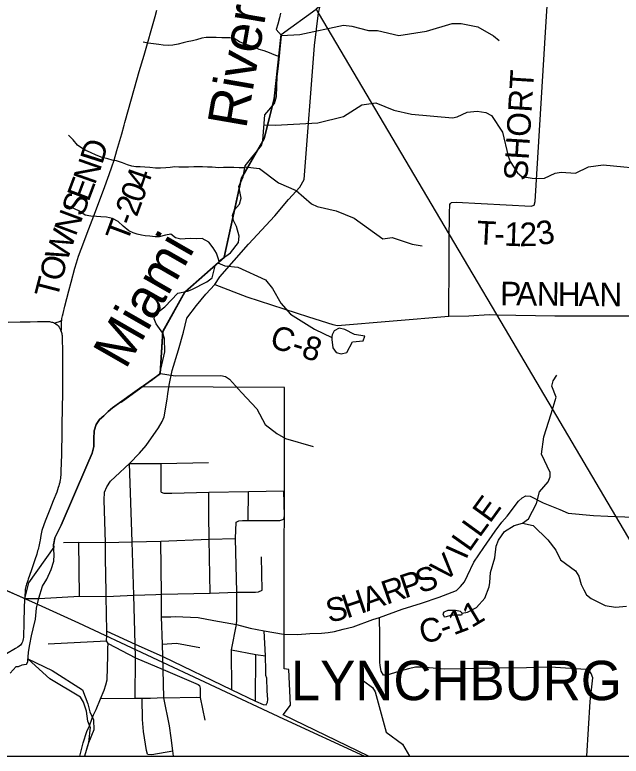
# Model space of a CAD drawing. Extents: x 0 to 48.6, y 0 to 22.
# Drawn here: x 3.311 to 4.768, y 14.1 to 15.882 of the extents above; entities that cross this region are included whole.
import ezdxf

# ---------------------------------------------------------------- set-up
doc = ezdxf.new("R2010")
doc.units = 0
for name, color, linetype in [('GM_X_City_Street', 7, 'Continuous'), ('GM_X_Corporation', 7, 'Continuous'), ('GM_X_Corporation_Text', 7, 'Continuous'), ('GM_X_County_Road', 7, 'Continuous'), ('GM_X_County_Road_Text', 7, 'Continuous'), ('GM_X_Major_River', 7, 'Continuous'), ('GM_X_Major_River_Text', 7, 'Continuous'), ('GM_X_Minor_Lake', 7, 'Continuous'), ('GM_X_Minor_River', 7, 'Continuous'), ('GM_X_Rail_Line', 7, 'Continuous'), ('GM_X_State_Route', 7, 'Continuous'), ('GM_X_Township_Road', 7, 'Continuous'), ('GM_X_Township_Road_Text', 7, 'Continuous'), ('SH_Data', 7, 'Continuous')]:
    doc.layers.add(name, color=color, linetype=linetype)

msp = doc.modelspace()

# ---------------------------------------------------------------- linework, layer by layer
at = {"layer": 'GM_X_City_Street'}
for p, q in [((3.6625, 14.7345), (3.6625, 14.8032)), ((3.8714, 14.6664), (3.8718, 14.736)), ((3.4662, 14.4845), (3.4646, 14.6148)), ((3.9053, 14.4987), (3.9036, 14.5793)), ((3.663, 14.4351), (3.6631, 14.4803)), ((3.3907, 14.3702), (3.5312, 14.3769)), ((3.889, 14.2321), (3.89, 14.3448)), ((3.7564, 14.2411), (3.7669, 14.1866))]:
    msp.add_line(p, q, dxfattribs=at)
for points in [[(3.586, 14.8032), (3.6625, 14.8032), (3.7764, 14.8056)], [(3.6002, 14.2383), (3.6006, 14.3367), (3.6, 14.3695), (3.5968, 14.4867), (3.5924, 14.6152), (3.586, 14.8032)], [(3.6625, 14.7345), (3.6686, 14.7321), (3.6879, 14.7325), (3.777, 14.7349), (3.8718, 14.736), (3.957, 14.7382)], [(3.9567, 14.6695), (3.9585, 14.6779), (3.957, 14.7382)], [(3.7798, 14.4922), (3.7778, 14.6217), (3.777, 14.6803), (3.777, 14.7349)], [(3.8429, 14.6627), (3.8492, 14.6656), (3.8575, 14.6664), (3.8714, 14.6664), (3.9478, 14.6665), (3.9567, 14.6695)], [(3.832, 14.2594), (3.8317, 14.3557), (3.8433, 14.4162), (3.8443, 14.427), (3.8444, 14.4941), (3.8409, 14.6235), (3.8429, 14.6627)], [(3.4274, 14.6139), (3.4646, 14.6148), (3.5285, 14.614), (3.5924, 14.6152), (3.6612, 14.6165), (3.7778, 14.6217), (3.8409, 14.6235)], [(3.6631, 14.4803), (3.6631, 14.4894), (3.6612, 14.6165)], [(3.5478, 14.4847), (3.5968, 14.4867), (3.6494, 14.4887), (3.6631, 14.4894), (3.7798, 14.4922), (3.8444, 14.4941), (3.8894, 14.494), (3.8963, 14.4953), (3.9053, 14.4987)], [(3.3688, 14.4789), (3.4662, 14.4845), (3.5299, 14.4839), (3.5478, 14.4847)], [(3.663, 14.4351), (3.6858, 14.4352), (3.6962, 14.4355), (3.7516, 14.4337), (3.7885, 14.4263), (3.8433, 14.4162), (3.8758, 14.4077), (3.91, 14.4016)], [(3.6691, 14.2402), (3.6671, 14.3086), (3.6665, 14.3392), (3.6652, 14.369), (3.663, 14.4351)], [(3.532, 14.4006), (3.6, 14.3695), (3.6665, 14.3392), (3.832, 14.2594), (3.889, 14.2321), (3.9073, 14.2244), (3.9147, 14.2234)], [(3.9137, 14.3062), (3.9127, 14.341), (3.91, 14.4016)], [(3.5346, 14.3706), (3.6006, 14.3367), (3.6671, 14.3086), (3.7514, 14.2726), (3.7543, 14.27), (3.7564, 14.2635), (3.7564, 14.2411)], [(3.6652, 14.369), (3.6989, 14.3713), (3.7549, 14.3615)], [(3.8317, 14.3557), (3.89, 14.3448), (3.9127, 14.341)], [(3.9147, 14.2234), (3.9175, 14.2298), (3.9185, 14.2365), (3.9172, 14.2567), (3.9163, 14.2875), (3.914, 14.2942), (3.9137, 14.3062)], [(3.6691, 14.2402), (3.7467, 14.2416), (3.7564, 14.2411)], [(3.6295, 14.1049), (3.6273, 14.1133), (3.6197, 14.1594), (3.6175, 14.1879), (3.617, 14.2387)], [(3.6295, 14.1049), (3.6399, 14.104), (3.6901, 14.1128)]]:
    msp.add_lwpolyline(points, dxfattribs=at)
at = {"layer": 'GM_X_Corporation'}
msp.add_lwpolyline([(5.0944, 14.1), (8.9, 14.1), (8.9, 19.5692), (8.5348, 19.2897), (7.2261, 18.2847), (6.9471, 18.0777), (6.5365, 17.7727), (5.8387, 17.2541), (5.5264, 17.0064), (4.6225, 16.3345), (4.044, 15.9033), (4.0346, 15.8959), (4.0398, 15.887), (4.3544, 15.3539), (4.4679, 15.1616), (4.7542, 14.6766)], close=True, dxfattribs=at)
for points in [[(3.2996, 14.2996), (3.3136, 14.3153), (3.3197, 14.3159), (3.3281, 14.3199), (3.3384, 14.3209), (3.3419, 14.3265), (3.3432, 14.3497), (3.3465, 14.3687), (3.3504, 14.3894), (3.3549, 14.4061), (3.3603, 14.4295), (3.3625, 14.4556), (3.3686, 14.4795), (3.377, 14.5086), (3.3872, 14.5255), (3.3983, 14.5488), (3.4048, 14.5688), (3.405, 14.584), (3.404, 14.6084), (3.4053, 14.6156), (3.407, 14.625), (3.422, 14.6555), (3.4837, 14.7987), (3.4964, 14.8285), (3.5005, 14.8447), (3.5009, 14.8629), (3.5012, 14.8819), (3.5061, 14.897), (3.5143, 14.909), (3.5243, 14.9183), (3.5348, 14.9284), (3.5452, 14.9373), (3.66, 15.0199), (3.6661, 15.1216), (3.7191, 15.2163), (3.814, 15.2998), (3.8557, 15.4901), (3.9098, 15.5849), (3.9337, 15.6801), (3.9507, 15.8348), (4.0346, 15.8959)], [(3.2996, 14.2996), (3.3136, 14.3153), (3.3197, 14.3159), (3.3281, 14.3199), (3.3384, 14.3209), (3.3419, 14.3265), (3.3432, 14.3497), (3.3465, 14.3687), (3.3504, 14.3894), (3.3549, 14.4061), (3.3603, 14.4295), (3.3625, 14.4556), (3.3686, 14.4795), (3.377, 14.5086), (3.3872, 14.5255), (3.3983, 14.5488), (3.4048, 14.5688), (3.405, 14.584), (3.404, 14.6084), (3.4053, 14.6156), (3.407, 14.625), (3.422, 14.6555), (3.4837, 14.7987), (3.4964, 14.8285), (3.5005, 14.8447), (3.5009, 14.8629), (3.5012, 14.8819), (3.5061, 14.897), (3.5143, 14.909), (3.5243, 14.9183), (3.5348, 14.9284), (3.5452, 14.9373), (3.66, 15.0199), (3.6661, 15.1216), (3.7191, 15.2163), (3.814, 15.2998), (3.8557, 15.4901), (3.9098, 15.5849), (3.9337, 15.6801), (3.9507, 15.8348), (4.0346, 15.8959)], [(3.3067, 14.3077), (3.3137, 14.3153), (3.3197, 14.3159), (3.3281, 14.3199), (3.3325, 14.3203), (3.3384, 14.3209), (3.3419, 14.3265), (3.3423, 14.334), (3.4003, 14.3059), (3.4732, 14.2593), (3.4859, 14.2261), (3.491, 14.2065), (3.4996, 14.1874), (3.5003, 14.1637), (3.4879, 14.1319), (3.4778, 14.1), (4.1608, 14.1), (3.9556, 14.1993), (3.9729, 14.2227), (3.9691, 14.3083), (3.9577, 14.3098), (3.9588, 14.9859), (3.6159, 14.9882), (3.5452, 14.9373), (3.5348, 14.9284), (3.5243, 14.9183), (3.5143, 14.909), (3.5061, 14.897), (3.5012, 14.8819), (3.5009, 14.8629), (3.5005, 14.8447), (3.4964, 14.8285), (3.4837, 14.7987), (3.422, 14.6555), (3.407, 14.625), (3.404, 14.6084), (3.4043, 14.6023), (3.3438, 14.5166), (3.3339, 14.4793), (3.0597, 14.5973)]]:
    msp.add_lwpolyline(points, dxfattribs=at)
at = {"layer": 'GM_X_County_Road'}
for p, q in [((3.3345, 14.4837), (3.3341, 14.4788)), ((3.91, 14.4016), (3.9564, 14.3934))]:
    msp.add_line(p, q, dxfattribs=at)
for points in [[(4.6086, 15.1588), (4.64, 15.1582), (4.8348, 15.1585), (4.9035, 15.1586), (4.9331, 15.1596), (5.071, 15.181), (5.1203, 15.1895), (5.1743, 15.1992), (5.2077, 15.2059), (5.2218, 15.2088), (5.2271, 15.216), (5.2317, 15.2361), (5.2617, 15.7172), (5.2803, 16.0116), (5.7212, 16.011), (6.0742, 16.1743), (6.2545, 16.2661)], [(3.7914, 15.2335), (3.8685, 15.2041), (4.016, 15.1564), (4.0751, 15.1376), (4.0861, 15.1349), (4.3538, 15.1576), (4.4016, 15.1589), (4.4502, 15.1614), (4.4681, 15.1611), (4.6086, 15.1588)], [(3.2944, 15.1433), (3.3236, 15.1437), (3.3472, 15.1442), (3.3652, 15.1445), (3.382, 15.1448), (3.3888, 15.1447), (3.3937, 15.1445), (3.3961, 15.1441), (3.399, 15.1436), (3.4014, 15.1429), (3.4036, 15.1421), (3.4056, 15.1411)], [(3.4056, 15.1411), (3.4063, 15.1408), (3.4094, 15.1389), (3.4123, 15.1366), (3.4149, 15.1341), (3.4172, 15.1313), (3.4191, 15.1283), (3.4208, 15.125), (3.4223, 15.1212)], [(3.4223, 15.1212), (3.4235, 15.1164), (3.4238, 15.114), (3.4243, 15.1109), (3.4245, 15.1072), (3.4248, 15.1029), (3.4251, 15.0744), (3.4256, 15.0185), (3.4255, 14.9744), (3.4239, 14.8967), (3.4233, 14.8619), (3.4229, 14.8433), (3.4226, 14.8272), (3.4219, 14.8026), (3.4218, 14.7971), (3.4216, 14.793), (3.4215, 14.7899), (3.4214, 14.7858), (3.4212, 14.7799), (3.421, 14.7757), (3.4206, 14.7716), (3.4202, 14.7671), (3.4197, 14.764), (3.4192, 14.7604), (3.4185, 14.7575), (3.4176, 14.7538), (3.4163, 14.7498), (3.4151, 14.7455), (3.4114, 14.735), (3.403, 14.7136), (3.3946, 14.6929), (3.3837, 14.6651), (3.3806, 14.6564), (3.3786, 14.6509), (3.3773, 14.6475), (3.3758, 14.6427), (3.3749, 14.6382), (3.3741, 14.6348), (3.3734, 14.6306), (3.3724, 14.625), (3.3715, 14.6196), (3.3708, 14.6158), (3.3701, 14.6123), (3.3692, 14.6079), (3.3684, 14.6044), (3.3674, 14.6007), (3.3665, 14.5971), (3.3655, 14.5937), (3.3632, 14.5858), (3.3584, 14.5717), (3.3496, 14.5459), (3.3429, 14.5258), (3.3419, 14.5224), (3.3404, 14.5176), (3.3391, 14.5132), (3.3382, 14.5103), (3.3373, 14.5076), (3.3366, 14.5045), (3.3359, 14.5012), (3.3357, 14.4984), (3.3345, 14.4837)], [(3.9564, 14.3934), (3.9901, 14.3924), (4.0193, 14.3947), (4.0477, 14.3953), (4.0633, 14.3974), (4.0788, 14.3998), (4.0996, 14.405), (4.1236, 14.4113), (4.1706, 14.4283), (4.1872, 14.4331), (4.2412, 14.4531), (4.2875, 14.4682), (4.33, 14.4823), (4.3721, 14.4979), (4.3815, 14.5077), (4.3915, 14.5191), (4.3982, 14.5345), (4.4133, 14.5664), (4.4378, 14.6016), (4.4649, 14.6406), (4.4813, 14.6622), (4.4939, 14.6769), (4.5042, 14.6905), (4.5129, 14.7029), (4.5211, 14.7128), (4.5297, 14.721), (4.5387, 14.7255), (4.549, 14.7251), (4.5805, 14.7087), (4.6203, 14.6931), (4.6407, 14.6845), (4.701, 14.6783), (4.7354, 14.6767), (4.7544, 14.676), (4.8433, 14.6729)], [(3.3341, 14.4788), (3.3332, 14.4543), (3.3326, 14.4245), (3.3321, 14.4083), (3.3318, 14.399), (3.3314, 14.3872), (3.3312, 14.385), (3.3309, 14.3818), (3.3301, 14.3782), (3.329, 14.3748), (3.3275, 14.3715), (3.3259, 14.369), (3.324, 14.3667), (3.3213, 14.3642), (3.3179, 14.3617), (3.3126, 14.3586), (3.2903, 14.3464)], [(3.3341, 14.4788), (3.3512, 14.4788), (3.3688, 14.4789)]]:
    msp.add_lwpolyline(points, dxfattribs=at)
at = {"layer": 'GM_X_Major_River'}
for points in [[(3.949, 15.8858), (3.9468, 15.8752), (3.9423, 15.8598), (3.939, 15.8466), (3.9516, 15.8321)], [(3.5649, 14.9509), (3.5728, 14.9568), (3.6132, 14.9861), (3.6416, 15.0052), (3.6594, 15.0198), (3.6711, 15.0721), (3.6703, 15.1043), (3.6663, 15.1169), (3.6507, 15.1391), (3.6455, 15.1513), (3.6468, 15.1615), (3.6709, 15.1802), (3.7021, 15.2132), (3.7257, 15.2179), (3.7359, 15.2215), (3.7722, 15.2401), (3.7845, 15.2498), (3.7921, 15.2789), (3.8044, 15.292), (3.8289, 15.3103), (3.8478, 15.3351), (3.8499, 15.3499), (3.8437, 15.3735), (3.8359, 15.3876), (3.8334, 15.3998), (3.8385, 15.413), (3.8505, 15.4269), (3.8545, 15.4413), (3.8491, 15.4691), (3.8593, 15.4928), (3.8642, 15.519), (3.9035, 15.5678), (3.9063, 15.5799), (3.9116, 15.6417), (3.9344, 15.6691), (3.9395, 15.6857), (3.9409, 15.7339), (3.9446, 15.7585), (3.9516, 15.8321)], [(3.6608, 15.0196), (3.6669, 15.1212), (3.7199, 15.216), (3.8149, 15.2994), (3.8565, 15.4898), (3.9106, 15.5846), (3.9345, 15.6798), (3.9515, 15.8345)], [(3.5666, 14.9513), (3.6608, 15.0196)]]:
    msp.add_lwpolyline(points, dxfattribs=at)
at = {"layer": 'GM_X_Minor_Lake'}
for points in [[(4.0725, 15.1017), (4.0748, 15.0812), (4.0827, 15.0705), (4.0952, 15.0669), (4.1085, 15.0706), (4.1221, 15.0958), (4.1479, 15.0985), (4.1515, 15.1099), (4.1265, 15.114), (4.1039, 15.126), (4.0903, 15.1288), (4.0777, 15.1225)], [(4.0777, 15.1225), (4.0733, 15.1131), (4.0727, 15.1086), (4.0725, 15.1017)], [(4.3426, 14.4347), (4.3479, 14.4361), (4.3582, 14.439), (4.3658, 14.4396), (4.3734, 14.4398), (4.378, 14.4397), (4.3829, 14.44), (4.3856, 14.4407), (4.386, 14.4434), (4.3815, 14.4476), (4.3736, 14.4497), (4.3672, 14.4502), (4.3573, 14.4504), (4.3512, 14.4505), (4.3455, 14.4476), (4.3413, 14.4458), (4.3393, 14.442)], [(4.3393, 14.442), (4.3426, 14.4347)]]:
    msp.add_lwpolyline(points, dxfattribs=at)
at = {"layer": 'GM_X_Minor_River'}
for points in [[(3.9516, 15.8321), (3.9957, 15.8346), (4.1003, 15.8572), (4.1208, 15.855), (4.1605, 15.8443), (4.1821, 15.8441), (4.2331, 15.8321), (4.3, 15.8426), (4.3617, 15.8609), (4.3834, 15.8614), (4.4231, 15.8533), (4.4611, 15.8316), (4.4747, 15.8204)], [(3.9468, 15.7808), (3.9339, 15.7862), (3.923, 15.7909), (3.9097, 15.7956), (3.898, 15.7984), (3.8871, 15.8035), (3.8765, 15.8074), (3.8644, 15.8114), (3.8504, 15.8173), (3.8376, 15.825), (3.8277, 15.8271), (3.8179, 15.8268), (3.8084, 15.8269), (3.7947, 15.8279), (3.7799, 15.8273), (3.7704, 15.8274), (3.7597, 15.826), (3.7475, 15.822), (3.738, 15.8195), (3.7247, 15.817), (3.7151, 15.8145), (3.7033, 15.8112), (3.69, 15.8095), (3.679, 15.8085), (3.6672, 15.809), (3.657, 15.8107), (3.6441, 15.812), (3.6308, 15.814), (3.6187, 15.8165)], [(3.9096, 15.6177), (3.9371, 15.6167), (4.0389, 15.6223), (4.1001, 15.6375), (4.1445, 15.6658), (4.1783, 15.6707), (4.2217, 15.6527), (4.2641, 15.6435), (4.3623, 15.6343), (4.3737, 15.6365), (4.3973, 15.648), (4.4213, 15.6503), (4.4421, 15.6474), (4.4564, 15.6404), (4.4825, 15.6003), (4.4965, 15.542), (4.5009, 15.5291), (4.5184, 15.5019), (4.5293, 15.4938), (4.5539, 15.4894), (4.5641, 15.4889), (4.5831, 15.4894), (4.6087, 15.5012), (4.6231, 15.5041), (4.658, 15.5018), (4.6893, 15.5166), (4.7247, 15.5215), (4.8406, 15.5102)], [(3.8633, 15.5144), (3.8501, 15.5143), (3.8372, 15.5149), (3.8125, 15.5152), (3.8007, 15.5146), (3.7852, 15.5156), (3.7734, 15.5157), (3.7616, 15.5166), (3.751, 15.5168), (3.7411, 15.5165), (3.7278, 15.5159), (3.7172, 15.5157), (3.705, 15.5158), (3.6948, 15.5163), (3.6838, 15.5153), (3.6739, 15.5143), (3.6606, 15.5134), (3.6488, 15.5131), (3.6348, 15.5152), (3.623, 15.5161), (3.612, 15.5163), (3.6017, 15.5168), (3.5915, 15.5184), (3.5813, 15.5216), (3.5692, 15.5259), (3.5548, 15.5311), (3.5446, 15.5331), (3.5344, 15.5363), (3.5204, 15.5391), (3.5064, 15.5446), (3.4924, 15.5512), (3.4815, 15.5563), (3.4713, 15.5614), (3.4615, 15.5691), (3.4507, 15.5818), (3.4394, 15.5929)], [(3.8637, 15.5163), (3.899, 15.5128), (3.9445, 15.4781), (3.9867, 15.4594), (4.0239, 15.4279), (4.0375, 15.4216), (4.0832, 15.4112), (4.1262, 15.3929), (4.1947, 15.3438), (4.2178, 15.3466), (4.2651, 15.3305), (4.2893, 15.3268)], [(3.8019, 15.2893), (3.7993, 15.2971), (3.7949, 15.3089), (3.7871, 15.3223), (3.7771, 15.3353), (3.7608, 15.3447), (3.7464, 15.3437), (3.7335, 15.3443), (3.7202, 15.344), (3.7095, 15.343), (3.697, 15.3459), (3.6858, 15.3551), (3.6725, 15.3526), (3.6576, 15.3483), (3.6481, 15.3484), (3.6352, 15.3497), (3.6242, 15.351), (3.6147, 15.3526), (3.6049, 15.3546), (3.595, 15.3578), (3.5845, 15.3625), (3.5709, 15.3741), (3.5589, 15.3856), (3.5454, 15.3922), (3.5313, 15.3955), (3.5173, 15.3964), (3.5071, 15.3969), (3.493, 15.3982), (3.4801, 15.4007), (3.4662, 15.41), (3.4538, 15.4158), (3.4405, 15.4213), (3.43, 15.4264)], [(3.7985, 15.2858), (3.8152, 15.2786), (3.8467, 15.2752), (3.9134, 15.2452), (3.9295, 15.2241), (3.9499, 15.189), (3.9731, 15.1629), (4.0307, 15.1265), (4.0727, 15.1068)], [(3.6608, 15.0196), (3.6961, 15.0145), (3.8054, 15.0154), (3.8171, 15.013), (3.8269, 15.0061), (3.8553, 14.9742), (3.8925, 14.9348)], [(4.5995, 14.9231), (4.6113, 14.9632), (4.601, 14.9891), (4.6042, 15.002), (4.6131, 15.0155)], [(3.8925, 14.9348), (3.9126, 14.8976), (3.9399, 14.8758), (3.9609, 14.864), (4.0273, 14.8445)], [(4.5302, 14.6599), (4.5449, 14.6703), (4.5642, 14.7075), (4.5716, 14.7358), (4.5921, 14.7597), (4.5969, 14.7714), (4.5971, 14.7816), (4.5764, 14.8257), (4.5817, 14.8677), (4.5995, 14.9231)], [(4.386, 14.4434), (4.3986, 14.4462), (4.4204, 14.4575), (4.4402, 14.4799), (4.4506, 14.5074), (4.452, 14.5173), (4.4539, 14.5415), (4.4641, 14.577), (4.4673, 14.6046), (4.4729, 14.6193), (4.4877, 14.6403), (4.5104, 14.6543), (4.5302, 14.6599), (4.5559, 14.6545), (4.5913, 14.6201), (4.6106, 14.595), (4.6219, 14.572), (4.6582, 14.5459), (4.6659, 14.5329), (4.6719, 14.513), (4.6781, 14.4996), (4.6847, 14.4881), (4.6956, 14.4788), (4.729, 14.4622), (4.7544, 14.4583), (4.7806, 14.4605)], [(3.4916, 14.1699), (3.4858, 14.184), (3.4829, 14.2084), (3.4757, 14.2301), (3.4684, 14.242), (3.3949, 14.2863), (3.3431, 14.3332)], [(4.1487, 14.281), (4.17, 14.2654), (4.1763, 14.2546), (4.2032, 14.1577), (4.2425, 14.1285), (4.2588, 14.1)], [(3.4916, 14.1699), (3.4879, 14.1328), (3.4781, 14.1)]]:
    msp.add_lwpolyline(points, dxfattribs=at)
at = {"layer": 'GM_X_Rail_Line'}
for points in [[(2.1, 15.0305), (2.2297, 14.9717), (2.5941, 14.811), (2.8918, 14.676), (3.3664, 14.4649)], [(3.3664, 14.4649), (3.4638, 14.4206), (3.956, 14.1901), (4.1513, 14.1)]]:
    msp.add_lwpolyline(points, dxfattribs=at)
at = {"layer": 'GM_X_State_Route'}
for points in [[(3.6785, 14.9709), (3.6813, 14.9916), (3.6889, 15.0268), (3.7036, 15.0771), (3.716, 15.119), (3.7243, 15.1527), (3.7475, 15.1836), (3.7699, 15.2102), (3.7914, 15.2335), (3.8031, 15.2519), (3.8721, 15.3307), (3.9352, 15.399), (3.968, 15.438), (3.9958, 15.4676), (4.0059, 15.4865), (4.0311, 15.8085), (4.04, 15.8865), (4.0443, 15.9028)], [(3.552, 14.7715), (3.586, 14.8032), (3.6104, 14.8283), (3.6261, 14.847), (3.6563, 14.8891), (3.6648, 14.9047), (3.6697, 14.9158), (3.6768, 14.9582), (3.6785, 14.9709)], [(3.5289, 14.5652), (3.5285, 14.614), (3.5255, 14.7152), (3.5265, 14.7345), (3.5315, 14.7477), (3.5407, 14.7609), (3.552, 14.7715)], [(3.5316, 14.3898), (3.532, 14.4006), (3.5299, 14.4839), (3.529, 14.5456), (3.5289, 14.5652)], [(3.534, 14.3423), (3.5343, 14.359), (3.5346, 14.3706), (3.5312, 14.3769), (3.5316, 14.3898)], [(3.4967, 14.1917), (3.4994, 14.199), (3.5058, 14.2123), (3.5163, 14.2378), (3.5256, 14.259), (3.5293, 14.2712), (3.5327, 14.2833), (3.534, 14.3423)], [(3.6691, 14.2402), (3.637, 14.239), (3.617, 14.2387), (3.6002, 14.2383), (3.5163, 14.2378)], [(3.6923, 14.1), (3.6901, 14.1128), (3.6867, 14.1441), (3.6822, 14.1731), (3.6691, 14.2402)], [(3.467, 14.1), (3.475, 14.1318), (3.4841, 14.1597), (3.4898, 14.1733), (3.4967, 14.1917)]]:
    msp.add_lwpolyline(points, dxfattribs=at)
at = {"layer": 'GM_X_Township_Road'}
for points in [[(4.3546, 15.3464), (4.3547, 15.3533), (4.3551, 15.3891), (4.3552, 15.4107), (4.356, 15.4202), (4.356, 15.4263), (4.3572, 15.4286), (4.3598, 15.4308), (4.3712, 15.4315), (4.5515, 15.4224), (4.5587, 15.4243), (4.5614, 15.4337), (4.587, 15.853), (4.6064, 16.1678), (4.6228, 16.334)], [(3.4233, 15.148), (3.424, 15.1523), (3.4247, 15.1556), (3.4253, 15.1585), (3.4265, 15.1638), (3.4309, 15.1819), (3.4407, 15.2185), (3.4464, 15.2395), (3.4552, 15.2732), (3.459, 15.2863), (3.464, 15.3016), (3.4703, 15.3191), (3.4889, 15.3679), (3.5002, 15.3988), (3.5239, 15.4609), (3.5376, 15.4983), (3.5441, 15.517), (3.5492, 15.533), (3.556, 15.5563), (3.5675, 15.5963), (3.5731, 15.6172), (3.5739, 15.6203), (3.5747, 15.6231), (3.598, 15.7059), (3.6096, 15.7458), (3.6212, 15.7852), (3.6476, 15.8784), (3.6519, 15.8929)], [(4.3538, 15.1576), (4.354, 15.2938), (4.3546, 15.3464)], [(3.4056, 15.1411), (3.4101, 15.1424), (3.4125, 15.1432), (3.4154, 15.144), (3.4177, 15.1448), (3.4193, 15.1457), (3.4233, 15.148)], [(3.4223, 15.1212), (3.4226, 15.1258), (3.4228, 15.1286), (3.4228, 15.1329), (3.4227, 15.1365), (3.4225, 15.1389), (3.4226, 15.1414), (3.4228, 15.1448), (3.4233, 15.148)], [(4.1881, 14.3259), (4.1876, 14.3388), (4.188, 14.3894), (4.1872, 14.4331)], [(4.2027, 14.2945), (4.1968, 14.2947), (4.1913, 14.304), (4.1883, 14.318), (4.1881, 14.3259)], [(4.5402, 14.3127), (4.4572, 14.3114), (4.344, 14.3092), (4.2878, 14.314), (4.2734, 14.3136), (4.2568, 14.3103), (4.2335, 14.3032), (4.2046, 14.2944), (4.2027, 14.2945)], [(4.6852, 14.1), (4.6852, 14.1), (4.6935, 14.2317), (4.6993, 14.2885), (4.6952, 14.2988), (4.6923, 14.3034), (4.6825, 14.3085), (4.5978, 14.3136), (4.5402, 14.3127)]]:
    msp.add_lwpolyline(points, dxfattribs=at)
at = {"layer": 'SH_Data'}
msp.add_line((2.1, 14.1), (8.9, 14.1), dxfattribs=at)

# ---------------------------------------------------------------- texts
at = {"layer": 'GM_X_Corporation_Text'}
msp.add_text('LYNCHBURG', height=0.0947, rotation=0, dxfattribs=at).set_placement((3.974, 14.2346))
at = {"layer": 'GM_X_County_Road_Text'}
for s, height, rotation, p in [('P', 0.0568, 359.5486, (4.4767, 15.1837)), ('A', 0.0568, 359.5523, (4.515, 15.1834)), ('N', 0.0568, 359.5523, (4.565, 15.183)), ('H', 0.0568, 359.5483, (4.615, 15.1826)), ('A', 0.0568, 359.5523, (4.665, 15.1822)), ('N', 0.0568, 359.5523, (4.715, 15.1818)), ('C-8', 0.05682, 342.2913, (3.9202, 15.0842)), ('E', 0.0568, 54.007, (4.4523, 14.6579)), ('L', 0.0568, 54.0481, (4.4273, 14.6235)), ('L', 0.0568, 54.6843, (4.4028, 14.5889)), ('I', 0.0568, 65.9273, (4.3948, 14.5702)), ('V', 0.0568, 42.2495, (4.3428, 14.5159)), ('P', 0.0568, 18.1983, (4.2477, 14.4789)), ('S', 0.0568, 18.3857, (4.2843, 14.4909)), ('R', 0.0568, 19.0231, (4.2038, 14.4637)), ('A', 0.0568, 19.5248, (4.1568, 14.447)), ('H', 0.0568, 18.4892, (4.1083, 14.4308)), ('S', 0.0568, 13.1581, (4.0654, 14.4205)), ('1', 0.0568, 30.9659, (4.4081, 14.4074)), ('1', 0.0568, 20.5179, (4.3651, 14.3902)), ('C', 0.0568, 12.5064, (4.2893, 14.3698)), ('-', 0.0568, 19.6001, (4.3422, 14.3821))]:
    msp.add_text(s, height=height, rotation=rotation, dxfattribs=at).set_placement(p)
at = {"layer": 'GM_X_Major_River_Text'}
for s, rotation, p in [('River', 80.1789, (3.8663, 15.6061)), ('Miami', 60.1802, (3.5768, 15.0275))]:
    msp.add_text(s, height=0.0947, rotation=rotation, dxfattribs=at).set_placement(p)
at = {"layer": 'GM_X_Township_Road_Text'}
for s, height, rotation, p in [('SHORT', 0.05682, 86.4371, (4.5421, 15.4821)), ('D', 0.0568, 72.2967, (3.5204, 15.5204)), ('N', 0.0568, 70.5896, (3.5032, 15.4715)), ('4', 0.0568, 71.1042, (3.6284, 15.4614)), ('E', 0.0568, 69.421, (3.4878, 15.4305)), ('0', 0.0568, 69.9351, (3.6159, 15.4274)), ('S', 0.0568, 69.3527, (3.4743, 15.3946)), ('2', 0.0568, 69.6437, (3.6037, 15.3943)), ('N', 0.0568, 69.4346, (3.4567, 15.3478)), ('-', 0.0568, 69.548, (3.5955, 15.3723)), ('T', 0.0568, 69.5237, (3.5806, 15.3325)), ('T', 0.0568, 357.0288, (4.4192, 15.3306)), ('1', 0.0568, 357.9377, (4.486, 15.3272)), ('2', 0.0568, 0.3289, (4.5235, 15.3259)), ('3', 0.0568, 10.9944, (4.57, 15.3272)), ('W', 0.0568, 71.2728, (3.4358, 15.2859)), ('-', 0.0568, 357.1974, (4.4618, 15.3283)), ('O', 0.0568, 74.8637, (3.423, 15.2385)), ('T', 0.0568, 75.5282, (3.4124, 15.1975))]:
    msp.add_text(s, height=height, rotation=rotation, dxfattribs=at).set_placement(p)

doc.saveas('drawing.dxf')
